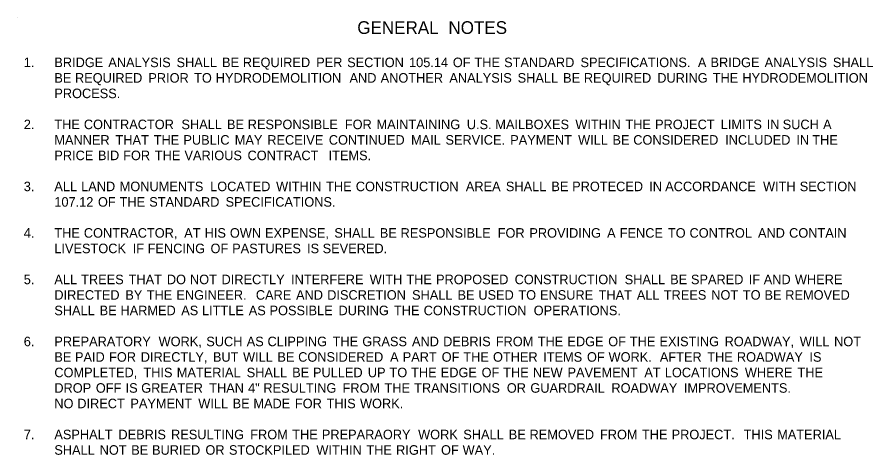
# Model space of a CAD drawing. Extents: x 1930579 to 1932220, y 596452 to 599479.
# Drawn here: x 1930760 to 1931351, y 599091 to 599394 of the extents above; entities that cross this region are included whole.
import ezdxf

# ---------------------------------------------------------------- set-up
doc = ezdxf.new("R2010")
doc.units = 0
doc.layers.add('Default', color=7, linetype='Continuous')
doc.layers.add('R_Border', color=7, linetype='Continuous')

msp = doc.modelspace()

# ---------------------------------------------------------------- linework, layer by layer
at = {"layer": 'R_Border'}
msp.add_line((1930759.59, 599393.53), (1930759.59, 599393.53), dxfattribs=at)

# ---------------------------------------------------------------- texts
at = {"layer": 'Default'}
for s, height, p in [('GENERAL', 8.8, (1930994.83, 599381.89)), (' NOTES', 8.8, (1931054.58, 599381.89)), ('1.', 6.6, (1930764.2, 599358.92)), ('BRIDGE', 6.6, (1930785.33, 599358.92)), (' ANALYSIS', 6.6, (1930820.2, 599358.92)), (' SHALL', 6.6, (1930867.39, 599358.92)), (' BE', 6.6, (1930898.84, 599358.92)), (' REQUIRED', 6.6, (1930913.21, 599358.92)), (' PER', 6.6, (1930963.96, 599358.92)), (' SECTION', 6.6, (1930985.36, 599358.92)), (' 105.14', 6.6, (1931028.15, 599358.92)), (' OF', 6.6, (1931058.46, 599358.92)), (' THE', 6.6, (1931073.4, 599358.92)), (' STANDARD', 6.6, (1931093.92, 599358.92)), (' SPECIFICATIONS.', 6.6, (1931146.72, 599358.92)), (' A', 6.6, (1931227.9, 599358.92)), (' BRIDGE', 6.6, (1931236.63, 599358.92)), (' ANALYSIS', 6.6, (1931274.06, 599358.92)), (' SHALL', 6.6, (1931321.24, 599358.92)), ('BE', 6.6, (1930785.33, 599348.2)), (' REQUIRED', 6.6, (1930797.14, 599348.2)), (' PRIOR', 6.6, (1930847.89, 599348.2)), (' TO', 6.6, (1930879.53, 599348.2)), (' HYDRODEMOLITION', 6.6, (1930894.49, 599348.2)), (' AND', 6.6, (1930986.99, 599348.2)), (' ANOTHER', 6.6, (1931008.53, 599348.2)), (' ANALYSIS', 6.6, (1931056.05, 599348.2)), (' SHALL', 6.6, (1931103.24, 599348.2)), (' BE', 6.6, (1931134.69, 599348.2)), (' REQUIRED', 6.6, (1931149.06, 599348.2)), (' DURING', 6.6, (1931199.81, 599348.2)), (' THE', 6.6, (1931238.17, 599348.2)), (' HYDRODEMOLITION', 6.6, (1931258.68, 599348.2)), ('PROCESS.', 6.6, (1930785.33, 599337.47)), ('2.', 6.6, (1930764.2, 599316.02)), ('THE', 6.6, (1930785.33, 599316.02)), (' CONTRACTOR', 6.6, (1930803.29, 599316.02)), (' SHALL', 6.6, (1930870.79, 599316.02)), (' BE', 6.6, (1930902.24, 599316.02)), (' RESPONSIBLE', 6.6, (1930916.61, 599316.02)), (' FOR', 6.6, (1930983.78, 599316.02)), (' MAINTAINING', 6.6, (1931005.68, 599316.02)), (' U.S.', 6.6, (1931068.12, 599316.02)), (' MAILBOXES', 6.6, (1931087.81, 599316.02)), (' WITHIN', 6.6, (1931143.19, 599316.02)), (' THE', 6.6, (1931177.77, 599316.02)), (' PROJECT', 6.6, (1931198.29, 599316.02)), (' LIMITS', 6.6, (1931243.71, 599316.02)), (' IN', 6.6, (1931275.5, 599316.02)), (' SUCH', 6.6, (1931286.53, 599316.02)), (' A', 6.6, (1931314.47, 599316.02)), ('MANNER', 6.6, (1930785.33, 599305.3)), (' THAT', 6.6, (1930825.17, 599305.3)), (' THE', 6.6, (1930851.63, 599305.3)), (' PUBLIC', 6.6, (1930872.14, 599305.3)), (' MAY', 6.6, (1930907.65, 599305.3)), (' RECEIVE', 6.6, (1930930.13, 599305.3)), (' CONTINUED', 6.6, (1930972.68, 599305.3)), (' MAIL', 6.6, (1931029.57, 599305.3)), (' SERVICE.', 6.6, (1931053.33, 599305.3)), (' PAYMENT', 6.6, (1931098.13, 599305.3)), (' WILL', 6.6, (1931145.09, 599305.3)), (' BE', 6.6, (1931168.84, 599305.3)), (' CONSIDERED', 6.6, (1931183.21, 599305.3)), (' INCLUDED', 6.6, (1931246.77, 599305.3)), (' IN', 6.6, (1931295.98, 599305.3)), (' THE', 6.6, (1931307.01, 599305.3)), ('PRICE', 6.6, (1930785.33, 599294.57)), (' BID', 6.6, (1930813.03, 599294.57)), (' FOR', 6.6, (1930830.47, 599294.57)), (' THE', 6.6, (1930852.37, 599294.57)), (' VARIOUS', 6.6, (1930872.88, 599294.57)), (' CONTRACT', 6.6, (1930916.47, 599294.57)), ('  ITEMS.', 6.6, (1930970.08, 599294.57)), ('3.', 6.6, (1930764.2, 599273.12)), ('ALL', 6.6, (1930785.33, 599273.12)), (' LAND', 6.6, (1930801.41, 599273.12)), (' MONUMENTS', 6.6, (1930828.08, 599273.12)), (' LOCATED', 6.6, (1930890.61, 599273.12)), (' WITHIN', 6.6, (1930936.24, 599273.12)), (' THE', 6.6, (1930970.82, 599273.12)), (' CONSTRUCTION', 6.6, (1930991.34, 599273.12)), (' AREA', 6.6, (1931067.43, 599273.12)), (' SHALL', 6.6, (1931095.13, 599273.12)), (' BE', 6.6, (1931126.58, 599273.12)), (' PROTECED', 6.6, (1931140.95, 599273.12)), (' IN', 6.6, (1931194.26, 599273.12)), (' ACCORDANCE', 6.6, (1931205.29, 599273.12)), (' WITH', 6.6, (1931272.95, 599273.12)), (' SECTION', 6.6, (1931298.32, 599273.12)), ('107.12', 6.6, (1930785.33, 599262.4)), (' OF', 6.6, (1930813.04, 599262.4)), (' THE', 6.6, (1930827.98, 599262.4)), (' STANDARD', 6.6, (1930848.5, 599262.4)), (' SPECIFICATIONS.', 6.6, (1930901.3, 599262.4)), ('4.', 6.6, (1930764.2, 599240.95)), ('THE', 6.6, (1930785.33, 599240.95)), (' CONTRACTOR,', 6.6, (1930803.29, 599240.95)), (' AT', 6.6, (1930872.66, 599240.95)), (' HIS', 6.6, (1930886.82, 599240.95)), (' OWN', 6.6, (1930904.27, 599240.95)), (' EXPENSE,', 6.6, (1930928.61, 599240.95)), (' SHALL', 6.6, (1930976.49, 599240.95)), (' BE', 6.6, (1931007.94, 599240.95)), (' RESPONSIBLE', 6.6, (1931022.31, 599240.95)), (' FOR', 6.6, (1931089.47, 599240.95)), (' PROVIDING', 6.6, (1931111.37, 599240.95)), (' A', 6.6, (1931165.11, 599240.95)), (' FENCE', 6.6, (1931173.84, 599240.95)), (' TO', 6.6, (1931207.16, 599240.95)), (' CONTROL', 6.6, (1931222.12, 599240.95)), (' AND', 6.6, (1931269.44, 599240.95)), (' CONTAIN', 6.6, (1931290.98, 599240.95)), ('LIVESTOCK', 6.6, (1930785.33, 599230.22)), (' IF', 6.6, (1930837.08, 599230.22)), (' FENCING', 6.6, (1930847.41, 599230.22)), (' OF', 6.6, (1930890.89, 599230.22)), (' PASTURES', 6.6, (1930905.84, 599230.22)), (' IS', 6.6, (1930957.63, 599230.22)), (' SEVERED.', 6.6, (1930968.42, 599230.22)), (' TREES', 6.6, (1930801.41, 599208.77)), (' DO', 6.6, (1930860.69, 599208.77)), (' NOT', 6.6, (1930876.68, 599208.77)), (' DIRECTLY', 6.6, (1930898.52, 599208.77)), (' PROPOSED', 6.6, (1931046.84, 599208.77)), (' CONSTRUCTION', 6.6, (1931101.18, 599208.77)), (' SHALL', 6.6, (1931177.28, 599208.77)), (' SPARED', 6.6, (1931223.1, 599208.77)), ('5.', 6.6, (1930764.2, 599208.77)), ('ALL', 6.6, (1930785.33, 599208.77)), (' THAT', 6.6, (1930834.24, 599208.77)), (' INTERFERE', 6.6, (1930946.62, 599208.77)), (' WITH', 6.6, (1931000.95, 599208.77)), (' THE', 6.6, (1931026.32, 599208.77)), (' BE', 6.6, (1931208.73, 599208.77)), (' IF', 6.6, (1931263.1, 599208.77)), (' AND', 6.6, (1931273.43, 599208.77)), (' WHERE', 6.6, (1931294.97, 599208.77)), ('DIRECTED', 6.6, (1930785.33, 599198.05)), (' BY', 6.6, (1930831.98, 599198.05)), (' THE', 6.6, (1930846.78, 599198.05)), (' ENGINEER.', 6.6, (1930867.29, 599198.05)), ('  CARE', 6.6, (1930919.78, 599198.05)), (' AND', 6.6, (1930950.03, 599198.05)), (' DISCRETION', 6.6, (1930971.57, 599198.05)), (' SHALL', 6.6, (1931030.25, 599198.05)), (' BE', 6.6, (1931061.7, 599198.05)), (' USED', 6.6, (1931076.08, 599198.05)), (' TO', 6.6, (1931103.77, 599198.05)), (' ENSURE', 6.6, (1931118.72, 599198.05)), (' THAT', 6.6, (1931159.23, 599198.05)), (' ALL', 6.6, (1931185.68, 599198.05)), (' TREES', 6.6, (1931204.32, 599198.05)), (' NOT', 6.6, (1931237.15, 599198.05)), (' TO', 6.6, (1931258.99, 599198.05)), (' BE', 6.6, (1931273.95, 599198.05)), (' REMOVED', 6.6, (1931288.32, 599198.05)), ('SHALL', 6.6, (1930785.33, 599187.32)), (' BE', 6.6, (1930814.22, 599187.32)), (' HARMED', 6.6, (1930828.6, 599187.32)), (' AS', 6.6, (1930870.63, 599187.32)), (' LITTLE', 6.6, (1930885.01, 599187.32)), (' AS', 6.6, (1930917.31, 599187.32)), (' POSSIBLE', 6.6, (1930931.7, 599187.32)), (' DURING', 6.6, (1930979.38, 599187.32)), (' THE', 6.6, (1931017.74, 599187.32)), (' CONSTRUCTION', 6.6, (1931038.26, 599187.32)), (' OPERATIONS.', 6.6, (1931114.35, 599187.32)), ('6.', 6.6, (1930764.2, 599165.87)), ('PREPARATORY', 6.6, (1930785.33, 599165.87)), (' WORK,', 6.6, (1930854.97, 599165.87)), (' SUCH', 6.6, (1930887.96, 599165.87)), (' AS', 6.6, (1930915.9, 599165.87)), (' CLIPPING', 6.6, (1930930.29, 599165.87)), (' THE', 6.6, (1930975.31, 599165.87)), (' GRASS', 6.6, (1930995.83, 599165.87)), (' AND', 6.6, (1931030.2, 599165.87)), (' DEBRIS', 6.6, (1931051.74, 599165.87)), (' FROM', 6.6, (1931088.15, 599165.87)), (' THE', 6.6, (1931117.17, 599165.87)), (' EDGE', 6.6, (1931137.68, 599165.87)), (' OF', 6.6, (1931165.89, 599165.87)), (' THE', 6.6, (1931180.84, 599165.87)), (' EXISTING', 6.6, (1931201.35, 599165.87)), (' ROADWAY,', 6.6, (1931246.38, 599165.87)), (' WILL', 6.6, (1931298.33, 599165.87)), (' NOT', 6.6, (1931322.08, 599165.87)), ('BE', 6.6, (1930785.33, 599155.15)), (' PAID', 6.6, (1930797.14, 599155.15)), (' FOR', 6.6, (1930820.74, 599155.15)), (' DIRECTLY,', 6.6, (1930842.64, 599155.15)), (' BUT', 6.6, (1930892.55, 599155.15)), (' WILL', 6.6, (1930913.37, 599155.15)), (' BE', 6.6, (1930937.12, 599155.15)), (' CONSIDERED', 6.6, (1930951.49, 599155.15)), (' A', 6.6, (1931015.05, 599155.15)), (' PART', 6.6, (1931023.78, 599155.15)), (' OF', 6.6, (1931050.75, 599155.15)), (' THE', 6.6, (1931065.7, 599155.15)), (' OTHER', 6.6, (1931086.21, 599155.15)), (' ITEMS', 6.6, (1931120.93, 599155.15)), (' OF', 6.6, (1931151.19, 599155.15)), (' WORK.', 6.6, (1931166.13, 599155.15)), ('  AFTER', 6.6, (1931199.14, 599155.15)), (' THE', 6.6, (1931234.36, 599155.15)), (' ROADWAY', 6.6, (1931254.88, 599155.15)), (' IS', 6.6, (1931305.02, 599155.15)), ('COMPLETED,', 6.6, (1930785.33, 599144.42)), (' THIS', 6.6, (1930844.47, 599144.42)), (' MATERIAL', 6.6, (1930867.55, 599144.42)), (' SHALL', 6.6, (1930915.9, 599144.42)), (' BE', 6.6, (1930947.36, 599144.42)), (' PULLED', 6.6, (1930961.73, 599144.42)), (' UP', 6.6, (1930999.67, 599144.42)), (' TO', 6.6, (1931014.64, 599144.42)), (' THE', 6.6, (1931029.6, 599144.42)), (' EDGE', 6.6, (1931050.11, 599144.42)), (' OF', 6.6, (1931078.32, 599144.42)), (' THE', 6.6, (1931093.26, 599144.42)), (' NEW', 6.6, (1931113.78, 599144.42)), (' PAVEMENT', 6.6, (1931137.75, 599144.42)), (' AT', 6.6, (1931190.86, 599144.42)), (' LOCATIONS', 6.6, (1931205.02, 599144.42)), (' WHERE', 6.6, (1931260.39, 599144.42)), (' THE', 6.6, (1931296.79, 599144.42)), ('DROP', 6.6, (1930785.33, 599133.7)), (' OFF', 6.6, (1930811.58, 599133.7)), (' IS', 6.6, (1930832.16, 599133.7)), (' GREATER', 6.6, (1930842.95, 599133.7)), (' THAN', 6.6, (1930889.97, 599133.7)), (' 4"', 6.6, (1930916.88, 599133.7)), (' RESULTING', 6.6, (1930927.41, 599133.7)), (' FROM', 6.6, (1930982.17, 599133.7)), (' THE', 6.6, (1931011.19, 599133.7)), (' TRANSITIONS', 6.6, (1931031.7, 599133.7)), (' OR', 6.6, (1931095.78, 599133.7)), (' GUARDRAIL', 6.6, (1931112.05, 599133.7)), (' ROADWAY', 6.6, (1931168.09, 599133.7)), (' IMPROVEMENTS.', 6.6, (1931218.23, 599133.7)), ('NO', 6.6, (1930785.33, 599122.97)), (' DIRECT', 6.6, (1930798.75, 599122.97)), (' PAYMENT', 6.6, (1930835.46, 599122.97)), (' WILL', 6.6, (1930882.42, 599122.97)), (' BE', 6.6, (1930906.17, 599122.97)), (' MADE', 6.6, (1930920.54, 599122.97)), (' FOR', 6.6, (1930949.25, 599122.97)), (' THIS', 6.6, (1930971.15, 599122.97)), (' WORK.', 6.6, (1930994.24, 599122.97)), ('7.', 6.6, (1930764.2, 599101.52)), ('ASPHALT', 6.6, (1930785.33, 599101.52)), (' DEBRIS', 6.6, (1930827.18, 599101.52)), (' RESULTING', 6.6, (1930863.59, 599101.52)), (' FROM', 6.6, (1930918.35, 599101.52)), (' THE', 6.6, (1930947.37, 599101.52)), (' PREPARAORY', 6.6, (1930967.88, 599101.52)), (' WORK', 6.6, (1931034.44, 599101.52)), (' SHALL', 6.6, (1931065.67, 599101.52)), (' BE', 6.6, (1931097.12, 599101.52)), (' REMOVED', 6.6, (1931111.49, 599101.52)), (' FROM', 6.6, (1931160.19, 599101.52)), (' THE', 6.6, (1931189.21, 599101.52)), (' PROJECT.', 6.6, (1931209.73, 599101.52)), ('  THIS', 6.6, (1931257.09, 599101.52)), (' MATERIAL', 6.6, (1931282.73, 599101.52)), ('SHALL', 6.6, (1930785.33, 599090.8)), (' NOT', 6.6, (1930814.22, 599090.8)), (' BE', 6.6, (1930836.07, 599090.8)), (' BURIED', 6.6, (1930850.44, 599090.8)), (' OR', 6.6, (1930887.35, 599090.8)), (' STOCKPILED', 6.6, (1930903.62, 599090.8)), (' WITHIN', 6.6, (1930964.11, 599090.8)), (' THE', 6.6, (1930998.7, 599090.8)), (' RIGHT', 6.6, (1931019.21, 599090.8)), (' OF', 6.6, (1931050.27, 599090.8)), (' WAY.', 6.6, (1931065.22, 599090.8))]:
    msp.add_text(s, height=height, dxfattribs=at).set_placement(p)

doc.saveas('drawing.dxf')
